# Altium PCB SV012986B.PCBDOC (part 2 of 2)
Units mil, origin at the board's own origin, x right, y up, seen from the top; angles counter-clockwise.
Board outline 2107 x 1920 mil, 4 copper layers (Top Layer, Mid-Layer 1, Mid-Layer 2, Bottom Layer), stack 59.6 mil thick; 51 components, 50 nets, 187 pads, 58 vias.
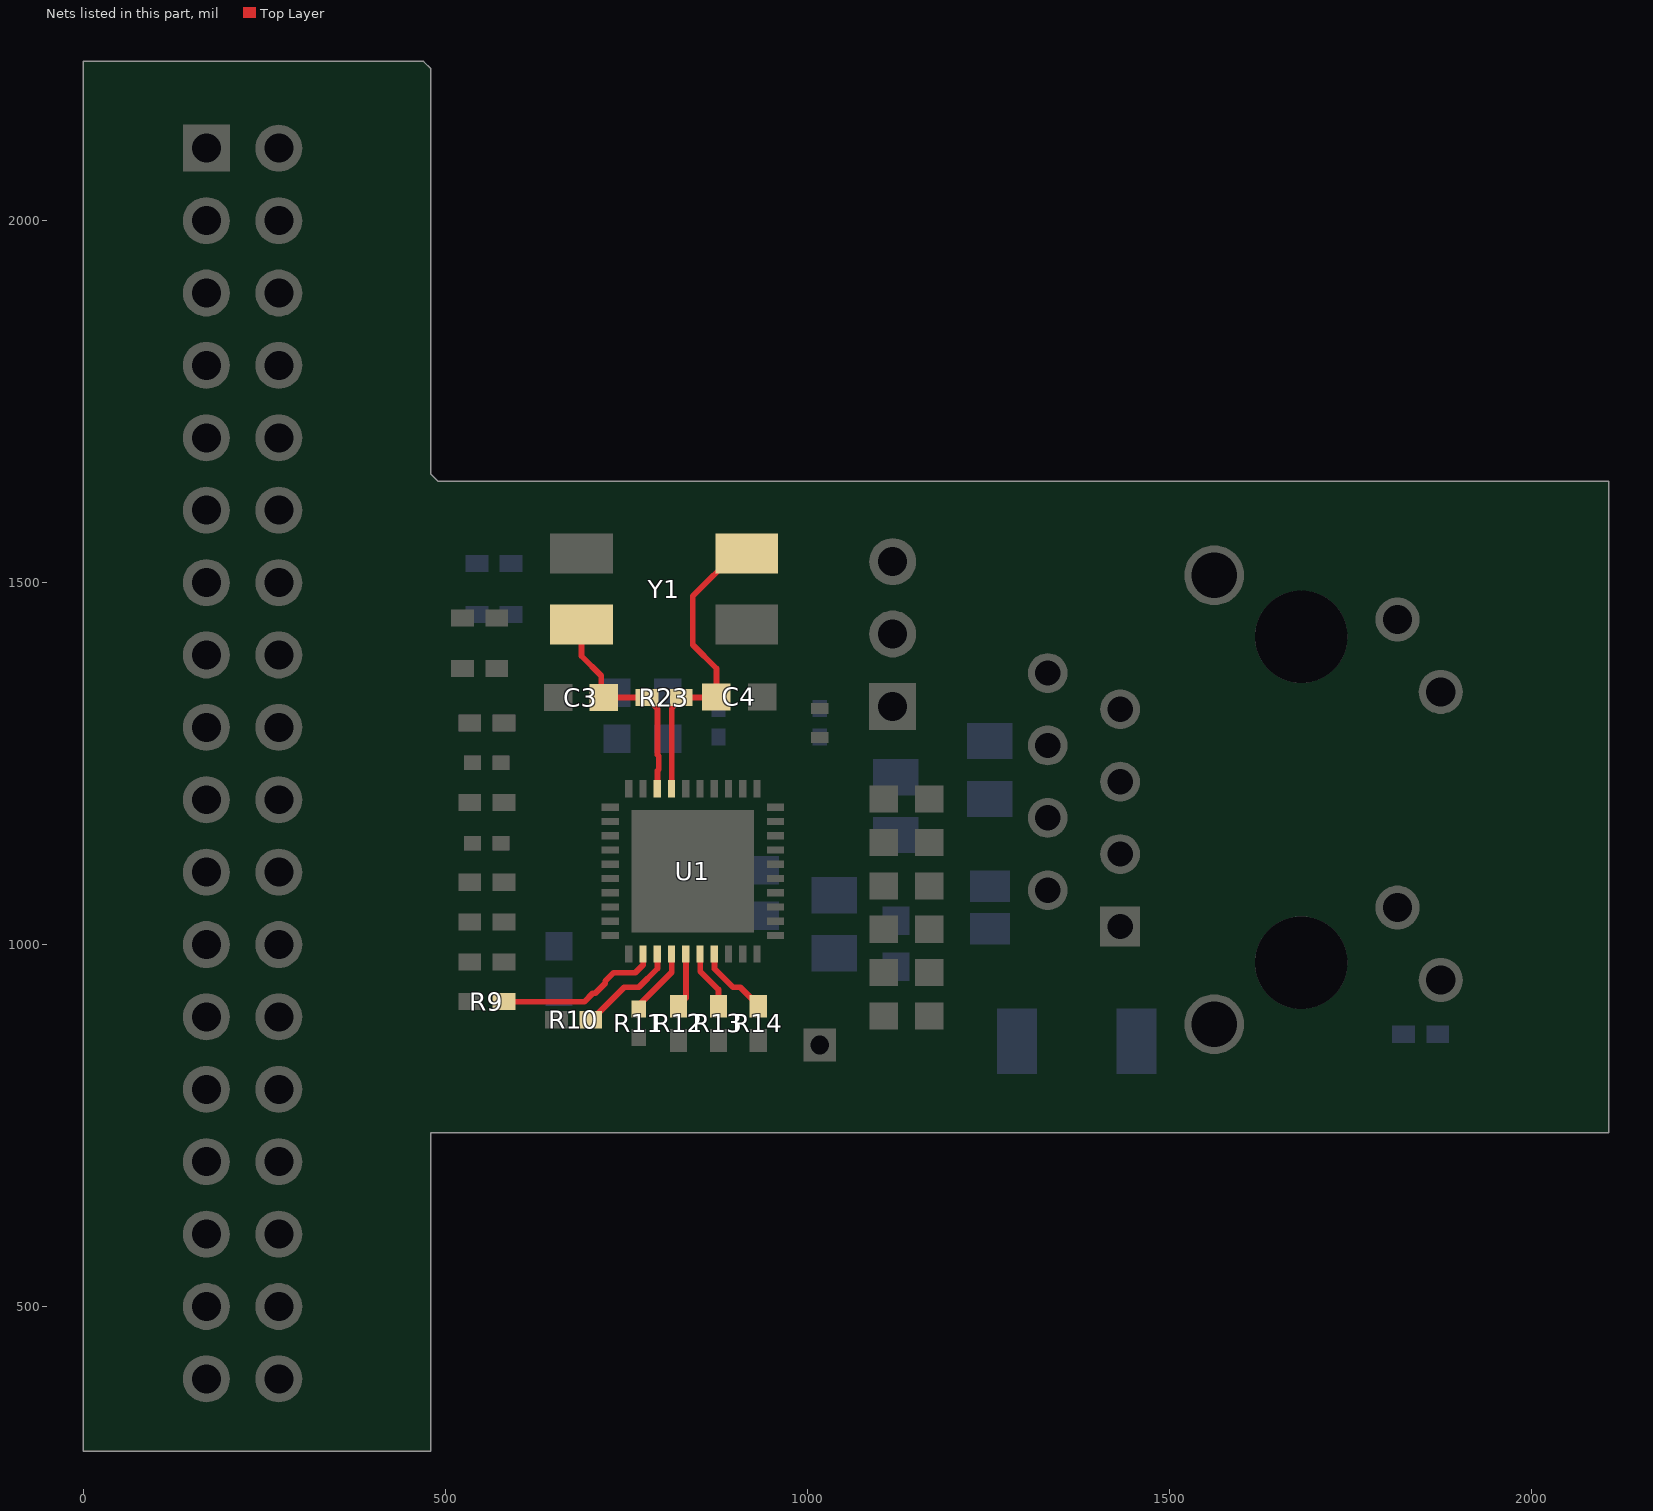
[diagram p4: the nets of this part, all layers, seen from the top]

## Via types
v1: diameter 23, hole 12, Top Layer to Bottom Layer, 50 vias
v2: diameter 19.68, hole 7.87, Top Layer to Bottom Layer, 8 vias

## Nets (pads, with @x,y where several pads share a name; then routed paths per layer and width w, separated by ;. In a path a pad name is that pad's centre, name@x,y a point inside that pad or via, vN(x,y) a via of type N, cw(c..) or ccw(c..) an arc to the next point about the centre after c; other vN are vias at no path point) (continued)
TX_CLK: R9.2 U1.2 | length 228.9
  Top Layer w8: R9.2@582.3,921.1 692.3,921.1 703.8,932.6 707.03,932.6 720.8,946.37 720.8,949.6 732.3,961.1 762.3,961.1 773.4,972.2 U1.2@773.4,986.93
TX_EN: R10.2 U1.3 | length 140.2
  Top Layer w8: R10.2@702.3,896.1 747.3,941.1 767.3,941.1 793.09,966.89 U1.3@793.09,986.93
TXD0: R11.2 U1.4 | length 89.7
  Top Layer w8: R11.2@767.3,916.1 812.77,961.57 U1.4@812.77,986.93
TXD1: R12.2 U1.5 | length 75
  Top Layer w8: R12.2@822.3,916.1 832.46,926.26 U1.5@832.46,986.93
TXD2: R13.2 U1.6 | length 81.3
  Top Layer w8: U1.6@852.14,986.93 852.14,962.86 877.3,937.7 R13.2@877.3,916.1
TXD3: R14.2 U1.7 | length 101.7
  Top Layer w8: U1.7@871.83,986.93 871.83,966.57 897.3,941.1 907.3,941.1 R14.2@932.3,916.1
X1: C3.1 R23.2 U1.28 Y1.1 | length 307.8
  Top Layer w8: Y1.1@688.13,1441.89 688.13,1398.45 715.3,1371.28 715.3,1341.1 777.3,1341.1 793.09,1325.31 793.09,1262.13 794.8,1260.42 794.8,1241.78 793.09,1240.07 U1.28@793.09,1215.27
X2: C4.1 R23.1 U1.27 Y1.3 | length 432.7
  Top Layer w8: U1.27@812.77,1215.27 812.77,1326.57 R23.1@827.3,1341.1 ; R23.1@825.92,1341.1 R23.1@827.3,1341.1 ; Y1.3@916.47,1540.31 900.72,1540.31 841.9,1481.49 841.9,1414 874.5,1381.4 C4.1@874.5,1342 873.6,1341.1 R23.1@827.3,1341.1
pads on no net: J1.20 J13.7 J13.MH1 J13.MH2 U1.8 U1.9 U1.10 U1.23

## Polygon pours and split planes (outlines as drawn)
GND on Bottom Layer "GND-GND" (solid, remove dead copper, pour order 12): 165 vertices, not listed, extent 7.3,351.1 1517.3,2151.1
GND_CHASSIS on Bottom Layer "BOTTOM-GND_CHASSIS" (solid, pour order 14): 1307.3,1576.1 1707.3,1576.1 1757.3,1526.1 1982.3,1526.1 2007.3,1501.1 2007.3,1026.1 1982.3,1001.1 1852.3,1001.1 1772.3,921.1 1772.3,856.1 1717.3,801.1 1467.3,801.1 1437.3,831.1 1437.3,906.1 1492.3,906.1 1557.3,971.1 1557.3,1251.1 1482.3,1326.1 1472.35,1326.1 1472.25,1328 1471.94,1331.48 1471.32,1334.91 1470.4,1338.28 1469.2,1341.55 1467.71,1344.71 1465.95,1347.72 1463.94,1350.57 1461.69,1353.24 1459.21,1355.7 1456.53,1357.93 1453.66,1359.92 1450.63,1361.65 1447.46,1363.11 1444.18,1364.3 1440.81,1365.19 1437.37,1365.78 1433.89,1366.07 1430.4,1366.05 1426.92,1365.74 1423.49,1365.12 1420.12,1364.2 1416.85,1363 1413.69,1361.51 1410.68,1359.75 1407.83,1357.74 1405.16,1355.49 1402.7,1353.01 1400.47,1350.33 1398.48,1347.46 1396.75,1344.43 1395.29,1341.26 1394.1,1337.98 1393.21,1334.61 1392.62,1331.17 1392.35,1328 1392.25,1326.1 1317.3,1326.1 1282.3,1361.1 1282.3,1551.1 1307.3,1576.1
PFBOUT on Bottom Layer "BOTTOM-PFBOUT" (solid, pour order 10): 767.3,1311.1 767.3,1267.95 766.02,1267.45 764.62,1266.85 763.27,1266.12 762,1265.27 760.8,1264.32 759.69,1263.27 758.68,1262.12 757.77,1260.89 756.97,1259.59 756.29,1258.22 755.73,1256.8 755.3,1255.34 755,1253.84 754.82,1252.32 754.78,1250.79 754.88,1249.27 755.1,1247.75 755.46,1246.27 755.94,1244.82 756.55,1243.42 757.28,1242.07 758.13,1240.8 759.08,1239.6 760.13,1238.49 761.28,1237.48 762.51,1236.57 763.81,1235.77 765.18,1235.09 766.6,1234.53 768.07,1234.1 769.56,1233.8 771.08,1233.62 772.61,1233.58 774.13,1233.68 775.65,1233.9 777.13,1234.26 778.58,1234.74 779.98,1235.35 780.67,1235.71 781.98,1236.42 787.3,1231.1 986.63,1231.1 986.98,1231.08 987.32,1231.04 987.67,1230.96 988,1230.86 988.32,1230.73 988.63,1230.56 988.92,1230.38 989.2,1230.16 989.46,1229.93 989.69,1229.67 989.91,1229.39 990.09,1229.1 990.26,1228.79 990.39,1228.47 990.49,1228.14 990.57,1227.79 990.61,1227.45 990.63,1227.1 990.61,1226.75 990.57,1226.41 990.49,1226.06 990.47,1225.99 990.11,1224.51 989.87,1222.99 989.77,1221.47 989.81,1219.94 989.97,1218.42 990.27,1216.92 990.7,1215.46 991.25,1214.03 991.93,1212.66 992.72,1211.35 993.63,1210.12 994.64,1208.97 995.74,1207.92 996.93,1206.96 998.2,1206.11 999.54,1205.38 1000.94,1204.76 1002.39,1204.27 1003.87,1203.91 1005.39,1203.67 1006.91,1203.57 1008.44,1203.61 1009.96,1203.77 1011.46,1204.07 1012.92,1204.5 1014.35,1205.05 1015.72,1205.73 1017.03,1206.52 1018.26,1207.43 1019.41,1208.44 1020.46,1209.54 1021.42,1210.73 1022.27,1212 1022.89,1213.11 1023.06,1213.41 1023.26,1213.7 1023.48,1213.97 1023.73,1214.22 1023.99,1214.45 1024.28,1214.65 1024.58,1214.82 1024.89,1214.97 1025.22,1215.1 1025.56,1215.19 1025.9,1215.25 1026.25,1215.28 1026.6,1215.29 1026.94,1215.26 1027.29,1215.2 1027.62,1215.11 1027.95,1215 1028.27,1214.85 1028.57,1214.68 1028.86,1214.48 1029.13,1214.26 1029.28,1214.12 1042.3,1201.1 1042.3,1126.1 1037.3,1121.1 1037.3,1106.12 1002.28,1106.12 1002.28,1071.1 932.3,1071.1 932.3,1079.08 962.32,1079.08 962.32,1119.12 932.3,1119.12 932.3,1186.1 927.3,1191.1 727.3,1191.1 702.3,1216.1 702.3,1311.1 712.3,1321.1 757.3,1321.1 767.3,1311.1
AVDD33 on Bottom Layer "BOTTOM-AVDD33" (solid, pour order 8): 1224.24,1234.92 1206.62,1217.3 1205.7,1217.38 1204.17,1217.44 1202.64,1217.37 1201.13,1217.17 1199.64,1216.83 1198.18,1216.36 1196.77,1215.77 1195.42,1215.06 1194.13,1214.24 1192.92,1213.3 1191.8,1212.26 1190.77,1211.13 1189.85,1209.92 1189.03,1208.63 1188.33,1207.27 1187.75,1205.85 1187.3,1204.39 1186.97,1202.9 1186.78,1201.38 1186.72,1199.86 1186.79,1198.33 1186.99,1196.82 1187.33,1195.32 1187.8,1193.87 1188.39,1192.46 1189.1,1191.11 1189.92,1189.82 1190.86,1188.61 1191.89,1187.49 1193.03,1186.46 1194.24,1185.53 1195.53,1184.72 1196.89,1184.02 1198.31,1183.44 1199.77,1182.98 1201.26,1182.66 1202.45,1182.49 1204.24,1182.31 1204.24,1157.53 1202.45,1157.35 1200.93,1157.13 1199.45,1156.78 1198,1156.3 1196.59,1155.69 1195.25,1154.96 1193.97,1154.12 1192.77,1153.17 1191.66,1152.12 1190.65,1150.98 1189.73,1149.76 1188.93,1148.45 1188.25,1147.09 1187.68,1145.67 1187.25,1144.2 1186.94,1142.71 1186.76,1141.19 1186.72,1139.66 1186.81,1138.13 1187.03,1136.62 1187.38,1135.13 1187.86,1133.68 1188.47,1132.28 1189.2,1130.94 1190.04,1129.66 1190.99,1128.46 1192.04,1127.35 1193.18,1126.33 1194.4,1125.42 1195.71,1124.62 1197.07,1123.94 1198.49,1123.37 1199.96,1122.93 1201.45,1122.63 1202.45,1122.49 1204.24,1122.31 1204.24,1114.92 1184.24,1094.92 1184.24,1009.92 1174.24,999.92 1084.24,999.92 1074.24,1009.92 1074.24,1114.92 1059.24,1129.92 1059.24,1174.92 1064.24,1179.92 1079.24,1179.92 1089.24,1189.92 1149.24,1189.92 1159.24,1199.92 1159.24,1324.92 1184.24,1349.92 1264.24,1349.92 1294.24,1319.92 1294.24,1244.92 1284.24,1234.92 1224.24,1234.92
GND on Mid-Layer 1 "GND-GND" (solid, remove dead copper, pour order 11): 165 vertices, not listed, extent 7.3,351.1 1517.3,2151.1
GND_CHASSIS on Top Layer "TOP-GND_CHASSIS" (solid, pour order 13): 160 vertices, not listed, extent 1282.3,821.1 2007.3,1576.1
3V3 on Mid-Layer 2 "3V3-3V3" (solid, pour order 9): 594 vertices, not listed, extent 277.3,676.1 1517.3,1681.1

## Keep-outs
Keep-Out Layer:
  text ".Layer_Name" at 577,-858.49 h60

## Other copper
Top Layer:
  text ".Layer_Name" at 577,-858.49 h60
Bottom Layer:
  text "UL94V-0" at 1527.3,1251.1 h45 r90
  text ".Layer_Name" at 577,-858.49 h60

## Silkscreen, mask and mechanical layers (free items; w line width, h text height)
Top Overlay:
  text ".Layer_Name" at 577,-858.49 h60
Bottom Overlay:
  region: 1641,1026 1641,1367 1541,1367 1541,1026
  text ".prj_title" at 103,1864 h80 r90
  text ".prj_number" at 2062,1459 h60 r90
  text ".pcb_rev" at 2062,974 h60 r90
  text ".Layer_Name" at 577,-858.49 h60
Top Paste:
  text ".Layer_Name" at 577,-858.49 h60
Bottom Paste:
  text ".Layer_Name" at 577,-858.49 h60
Top Solder:
  text ".Layer_Name" at 577,-858.49 h60
  text ".Layer_Name" at 577,-858.49 h60
Bottom Solder:
  text ".Layer_Name" at 577,-858.49 h60
Drill Guide:
  text ".Layer_Name" at 577,-858.49 h60
M1 Board Outline:
  the board outline again, w10
  text ".Layer_Name" at 577,-858.49 h60
M2 Board Dimensions:
  rectangle: 0,-275 125,-150
  rectangle: 125,-400 500,-275
  lines w7: 0,-275 1000,-275 ; 0,-150 0,-400 1000,-400 1000,-150 ; 125,-400 125,-150 ; 250,-400 250,-150 ; 500,-400 500,-150 ; 750,-400 750,-150
  text ".Layer_Name" at 577,-858.49 h60
M3 3D STEP Top:
  text ".Layer_Name" at 577,-858.49 h60
M4 3D STEP Bottom:
  text ".Layer_Name" at 577,-858.49 h60
M5 Assembly Top:
  lines w10: -292,-930.17 6308,-930.17 ; -292,-726.83 6310,-726.83 ; -292,-523.5 -292,-1133.5 3713,-1133.5 6310,-1133.5 6310,-523.5 -291.5,-523.5 -291.5,-1133.5 1284,-1133.5 ; 2173,-1133.5 2173,-523.5 ; 3440,-726.83 3440,-523.5 ; 4280,-726.83 4280,-523.5 ; 4902,-1140 4902,-937.17
  text "COMPONENTS MARKED 'DNP' SHOULD NOT BE POPULATED." at 1153.5,-318.5 h60
  text "ASSEMBLY VARIANT:" at 1153,-434 h60
  text ".VariantName" at 2189,-434 h60
  text "PCB VIEWED FROM TOP SIDE" at -228.5,-655.67 h60
  text "BOARD #:" at 2248,-655.67 h60
  text ".PRJ_Number" at 2793.5,-655.67 h60
  text "REV:" at 3638,-655.67 h60
  text ".PCB_Rev" at 3929.5,-655.67 h60
  text "SVN REV:" at 4476,-655.67 h60
  text ".VersionControl_RevNumber" at 4982,-655.67 h60
  text "PLOT NAME =" at -228.5,-1064.34 h60
  text ".plot_File_Name" at 577,-1064.34 h60
  text "GENERATED    :" at 2250,-1064.34 h60
  text ".Print_Date" at 3119.5,-1064.34 h60
  text ".Print_Time" at 3848.5,-1064.34 h60
  text "TEXAS INSTRUMENTS" at 5113,-1064.34 h60
M6 Assembly Bottom:
  lines w10: -292.5,-727.33 6309.5,-727.33 ; -290.5,-930.67 6309.5,-930.67 ; 1115.5,-1140.5 1115.5,-937.67 ; 1737.5,-727.33 1737.5,-524 ; 2577.5,-727.33 2577.5,-524 ; 3844.5,-1134 3844.5,-524 ; 4733.5,-1134 6309,-1134 6309,-524 -292.5,-524 -292.5,-1134 2304.5,-1134 6309.5,-1134 6309.5,-524
  text "COMPONENTS MARKED 'DNP' SHOULD NOT BE POPULATED." at 6102,-318 h60
  text ".VariantName" at 5058,-434 h60
  text "ASSEMBLY VARIANT:" at 6097,-434 h60
  text ".VersionControl_RevNumber" at 1035.5,-656.17 h60
  text "SVN REV:" at 1541.5,-656.17 h60
  text ".PCB_Rev" at 2088,-656.17 h60
  text "REV:" at 2379.5,-656.17 h60
  text ".PRJ_Number" at 3224,-656.17 h60
  text "BOARD #:" at 3769.5,-656.17 h60
  text "PCB VIEWED FROM BOTTOM SIDE" at 6246,-656.17 h60
  text "TEXAS INSTRUMENTS" at 904.5,-1064.84 h60
  text ".Print_Time" at 2169,-1064.84 h60
  text ".Print_Date" at 2898,-1064.84 h60
  text "GENERATED    :" at 3767.5,-1064.84 h60
  text ".plot_File_Name" at 5440.5,-1064.84 h60
  text "PLOT NAME =" at 6246,-1064.84 h60
M9 Title Sheet:
  drawing of 57 lines, arcs and shapes, not listed
  text "1" at 739.84,8036.5 h70
  text "2" at 3235.5,8036.5 h70
  text "3" at 5724.84,8036.5 h70
  text "4" at 8231.51,8036.5 h70
  text "5" at 10730.5,8036.5 h70
  text "6" at 13235.5,8036.5 h70
  text "A" at -416.5,6893.5 h70
  text "A" at 14383.5,6893.5 h70
  text "B" at -416.5,4513.5 h70
  text "B" at 14383.5,4513.5 h70
  text "C" at -416.5,2138.5 h70
  text "C" at 14383.5,2138.5 h70
  text "PROJECT TITLE:" at 11343.5,277.5 h45
  text ".PRJ_Title" at 11393.5,144.17 h70
  text "DESIGNED FOR:" at 11343.5,-23.5 h45
  text ".PRJ_Customer" at 11393.5,-163.5 h70
  text "D" at -416.5,-231.5 h70
  text "D" at 14383.5,-231.5 h70
  text "FILE NAME:" at 11343.5,-323.5 h45
  text ".PCB_File_Name_No_Path" at 11393.5,-443.5 h70
  text "Texas Instruments (TI) and/or its licensors do not warrant the accuracy or completeness of this specification" at 6374,-605.34 h45
  text "ENGINEER:" at 11343.5,-613.5 h45
  text "LAYOUT BY:" at 12848.5,-613.5 h45
  text "or any information contained therein. TI and/or its licensors do not warrant that this design will meet" at 6329.01,-718 h45
  text ".PRJ_Engineer" at 11393.5,-768.49 h70
  text ".PCB_Layout" at 12899,-768.49 h70
  text "the specifications, will be suitable for your application or fit for any particular purpose, or will operate in" at 6329.01,-830.67 h45
  text ".Layer_Name" at 577,-858.49 h60
  text "ALTIUM DESIGNER VERSION:" at 12848.5,-923.5 h45
  text "an implementation. TI and/or its licensors do not warrant that the design is production worthy. You should" at 6329.01,-943.33 h45
  text "completely validate and test your design implementation to confirm the system functionality for your application." at 6374,-1056 h45
  text ".print_Scale" at 11393.5,-1056.83 h70
  text ".Application_BuildNumber" at 12899,-1056.83 h70
  text "1" at 739.84,-1263.5 h70
  text "2" at 3235.5,-1263.5 h70
  text "3" at 5724.84,-1263.5 h70
  text "4" at 8231.51,-1263.5 h70
  text "5" at 10730.5,-1263.5 h70
  text "6" at 13235.5,-1263.5 h70
M10 Fab Notes:
  drawing of 185 lines, arcs and shapes, not listed
  text "DESIGN INFORMATION" at 12381.02,5910 h60
  text "MIN. TRACK WIDTH:" at 11736.46,5730 h60
  text "8" at 12832.7,5730 h60
  text "MIL" at 12987.46,5730 h60
  text "MIN. CLEARANCE:" at 11736.46,5598 h60
  text "0.2" at 12772.7,5598 h60
  text "mm" at 12987.46,5598 h60
  text "MIN. VIA PAD SIZE:" at 11736.46,5466 h60
  text "24" at 12802.71,5466 h60
  text "MIL" at 12987.46,5466 h60
  text "0.05mm (2MIL)" at 12431.46,5324.29 h60
  text "MINIMUM ANNULAR RING" at 11407.23,5320 h60
  text "EXTERNAL" at 13139.46,5320 h60
  text "PER" at 11607.23,5202 h60
  text "IPC-D-275 CLASS 2 LEVEL C" at 11827.23,5202 h60
  text "MIL, HOLES" at 13315.46,5089.71 h60
  text "+/-" at 12923,5089 h60
  text "+/-" at 13777,5089 h60
  text "REGISTRATION TOLERANCES:" at 11407.23,5084 h60
  text "METAL" at 12607,5084 h60
  text "5" at 13183.2,5084 h60
  text "3" at 14016.2,5084 h60
  text "MIL" at 14132.46,5084 h60
  text "MATERIAL:" at 11332.46,4874.54 h60
  text "FR-4 High Tg" at 12318.9,4734.21 h60
  text "FR-408" at 11753.46,4725.64 h60
  text "X" at 12165.46,4725.64 h60
  text "OTHER" at 13241.46,4725.64 h60
  text "62 MIL (1.6mm) +/-10%" at 12073.56,4562.92 h60
  text "THICKNESS:" at 11407.23,4558.64 h60
  text "X" at 11945.4,4558.64 h60
  text "OTHER" at 13358.46,4558.64 h60
  text "TOLERANCE:" at 11407.23,4400.64 h60
  text "X" at 12246.53,4400.64 h60
  text "ANSI IPC-6012 TYPE 3 CLASS 2" at 12433.48,4400.64 h60
  text "OTHER +/-" at 12433.46,4244.64 h60
  text "BOW & TWIST:" at 11407.23,4087.64 h60
  text "X" at 12246.53,4087.64 h60
  text "ANSI IPC-6012 TYPE 3 CLASS 2" at 12433.48,4087.64 h60
  text "OTHER +/-" at 12433.46,3929.13 h60
  text "DRILLING:" at 11332.46,3790.64 h60
  text "REFERENCE:" at 11407.23,3673.64 h60
  text "X" at 12055.46,3673.64 h60
  text "AS SHOWN" at 12242.46,3673.64 h60
  text "X" at 12956.46,3673.64 h60
  text "NC_DRILL FILES" at 13093.46,3673.64 h60
  text "PTH MIN COPPER THICKNESS:" at 11407.23,3515.64 h60
  text "X" at 12757.46,3515.64 h60
  text "1MIL" at 12894.46,3515.64 h60
  text "OTHER" at 13391.46,3515.64 h60
  text "BOARD FINISH:" at 11332.46,3356.64 h60
  text "SILKSCREEN:" at 11487.68,3238.64 h60
  text "X" at 12436.46,3238.64 h60
  text "TOP" at 12562.46,3238.64 h60
  text "X" at 12946.46,3238.64 h60
  text "BOTTOM" at 13073.46,3238.64 h60
  text "SILKSCREEN COLOR:" at 11487.68,3071.64 h60
  text "X" at 12435.42,3071.64 h60
  text "WHITE" at 12562.46,3071.64 h60
  text "OTHER" at 13073.46,3071.64 h60
  text "SOLDER RESIST COLOR:" at 11487.68,2901.64 h60
  text "X" at 12055.42,2742.44 h60
  text "GREEN" at 12182.46,2742.44 h60
  text "BLUE" at 12773.46,2742.44 h60
  text "OTHER" at 13311.46,2742.44 h60
  text "IMMERSION GOLD (ENIG)" at 12393.46,2553.92 h60
  text "ENEPIG" at 13731,2550.64 h60
  text "SURFACE FINISH:" at 11332.46,2549.64 h60
  text "X" at 12206.51,2549.64 h60
  text "IMM. TIN/SILVER OR EQUIV" at 11662,2392.64 h60
  text "OTHER" at 13093.46,2392.64 h60
  text "ARRAY/PANEL:" at 11332.46,2213.64 h60
  text "CUT AND TRIM PER MECH LAYER 1" at 12393.46,2209.35 h60
  text "N.C. ROUTE" at 12393.46,2057.64 h60
  text "X" at 13072.46,2057.64 h60
  text "V. SCORE" at 13259.46,2057.64 h60
  text "CERTIFICATION:" at 11332.46,1920.64 h60
  text "MATERIALS AND WORKMANSHIP FOR ALL PCBS" at 12057.46,1920.64 h60
  text "TO MEET OR EXCEED THE REQUIREMENTS OF:" at 12057.46,1822.64 h60
  text "X" at 11683.96,1686.13 h60
  text "ANSI IPC-A-600F CLASS ->" at 11822.96,1686.13 h60
  text "X" at 13462.02,1686.13 h60
  text "2" at 13580.96,1686.14 h60
  text "1" at 13265.96,1684.64 h60
  text "3" at 13934.96,1684.64 h60
  text "X" at 11686.02,1526.64 h60
  text "UL 94V-0" at 11822.96,1526.64 h60
  text "X" at 12498.02,1526.64 h60
  text "RoHS" at 12634.96,1526.64 h60
  text "OTHER" at 13279.36,1526.64 h60
  text "PER ORDER" at 13676.42,1526.64 h60
  text "ADDITIONAL REQUIREMENTS:" at 11332.46,1385.64 h60
  text "MICROSECTION:" at 11407.23,1270.64 h60
  text "YES" at 12312.96,1270.64 h60
  text "REQUIRED" at 13174.46,1114.49 h60
  text "BARE BOARD ELEC. TEST:" at 11407.23,1111.64 h60
  text "NONE" at 12712.96,1111.64 h60
  text "X" at 13047.46,1111.64 h60
  text "PER ORDER" at 13766.46,1111.64 h60
  text "MANUFACTURER'S UL:" at 11407.23,954.64 h60
  text "RAIL" at 12572.96,950.35 h60
  text "METAL" at 13064.77,950.35 h60
  text "X" at 13440,950 h60
  text "SILK" at 13576.46,950.35 h60
  text ".Layer_Name" at 577,-858.49 h60
M11 Gerber Information:
  lines w10: -292,-930.17 6308,-930.17 ; -292,-726.83 6310,-726.83 ; -292,-523.5 -292,-1133.5 3713,-1133.5 6310,-1133.5 6310,-523.5 -291.5,-523.5 -291.5,-1133.5 1284,-1133.5 ; 2173,-1133.5 2173,-523.5 ; 3440,-726.83 3440,-523.5 ; 4280,-726.83 4280,-523.5 ; 4902,-1140 4902,-937.17
  text "ALL ARTWORK VIEWED FROM TOP SIDE" at -228.5,-655.67 h60
  text "BOARD #:" at 2248,-655.67 h60
  text ".PRJ_Number" at 2793.5,-655.67 h60
  text "REV:" at 3638,-655.67 h60
  text ".PCB_Rev" at 3929.5,-655.67 h60
  text "SVN REV:" at 4476,-655.67 h60
  text ".VersionControl_RevNumber" at 4982,-655.67 h60
  text "LAYER NAME =" at -228.5,-858.49 h60
  text "PLOT NAME =" at -228.5,-1064.34 h60
  text ".plot_File_Name" at 577,-1064.34 h60
  text "GENERATED    :" at 2250,-1064.34 h60
  text ".Print_Date" at 3119.5,-1064.34 h60
  text ".Print_Time" at 3848.5,-1064.34 h60
  text "TEXAS INSTRUMENTS" at 5113,-1064.34 h60
M12 Stackup:
  drawing of 295 lines, arcs and shapes, not listed
  text "Layer" at 4550,5940 h60
  text "Name" at 4959.91,5940 h60
  text "Material" at 5889.66,5940 h60
  text "Thickness" at 6749.42,5940 h60
  text "Constant" at 7399.26,5940 h60
  text "Board Layer Stack" at 7969.12,5940 h60
  text "1" at 4550,5820 h60
  text "Top Overlay" at 4959.91,5820 h60
  text "2" at 4550,5700 h60
  text "Top Solder" at 4959.91,5700 h60
  text "Solder Resist" at 5889.66,5700 h60
  text "0.40mil" at 6749.42,5700 h60
  text "3.5" at 7399.26,5700 h60
  text "3" at 4550,5580 h60
  text "Top Layer" at 4959.91,5580 h60
  text "Copper" at 5889.66,5580 h60
  text "1.40mil" at 6749.42,5580 h60
  text "4" at 4550,5460 h60
  text "Dielectric1" at 4959.91,5460 h60
  text "FR-4" at 5889.66,5460 h60
  text "4.00mil" at 6749.42,5460 h60
  text "4.8" at 7399.26,5460 h60
  text "5" at 4550,5340 h60
  text "Mid-Layer 1" at 4959.91,5340 h60
  text "Copper" at 5889.66,5340 h60
  text "1.40mil" at 6749.42,5340 h60
  text "6" at 4550,5220 h60
  text "Dielectric3" at 4959.91,5220 h60
  text "FR-4" at 5889.66,5220 h60
  text "46.00mil" at 6749.42,5220 h60
  text "4.8" at 7399.26,5220 h60
  text "7" at 4550,5100 h60
  text "Mid-Layer 2" at 4959.91,5100 h60
  text "Copper" at 5889.66,5100 h60
  text "1.40mil" at 6749.42,5100 h60
  text "8" at 4550,4980 h60
  text "Dielectric2" at 4959.91,4980 h60
  text "FR-4" at 5889.66,4980 h60
  text "4.00mil" at 6749.42,4980 h60
  text "4.8" at 7399.26,4980 h60
  text "9" at 4550,4860 h60
  text "Bottom Layer" at 4959.91,4860 h60
  text "Copper" at 5889.66,4860 h60
  text "1.40mil" at 6749.42,4860 h60
  text "10" at 4550,4740 h60
  text "Bottom Solder" at 4959.91,4740 h60
  text "Solder Resist" at 5889.66,4740 h60
  text "0.40mil" at 6749.42,4740 h60
  text "3.5" at 7399.26,4740 h60
  text "11" at 4550,4620 h60
  text "Bottom Overlay" at 4959.91,4620 h60
  text ".Layer_Name" at 577,-858.49 h60
M13 Component Bodies Top:
  text ".Layer_Name" at 577,-858.49 h60
M14 Component Bodies Bottom:
  text ".Layer_Name" at 577,-858.49 h60
M15 Courtyards Top:
  text ".Layer_Name" at 577,-858.49 h60
M16 Courtyards Bottom:
  text ".Layer_Name" at 577,-858.49 h60
Drill Drawing:
  circle w1: c5692.73,3071.68 r24.89
  lines w1: 5667.84,2175.67 5692.73,2150.78 5717.62,2175.67 5692.73,2200.56 5667.84,2175.67 ; 5667.84,2300.12 5667.84,2312.56 5680.28,2325.01 5667.84,2337.45 5667.84,2349.9 5680.28,2349.9 5692.73,2337.45 5705.17,2349.9 5717.62,2349.9 5717.62,2337.45 5705.17,2325.01 5717.62,2312.56 5717.62,2300.12 5705.17,2300.12 5692.73,2312.56 5680.28,2300.12 5667.84,2300.12 ; 5667.84,2461.9 5680.28,2461.9 5680.28,2449.45 5705.17,2449.45 5705.17,2461.9 5717.62,2461.9 5717.62,2486.79 5705.17,2486.79 5705.17,2499.23 5680.28,2499.23 5680.28,2486.79 5667.84,2486.79 5667.84,2461.9 ; 5667.84,2598.79 5692.73,2611.23 5717.62,2598.79 5705.17,2623.68 5717.62,2648.57 5692.73,2636.12 5667.84,2648.57 5680.28,2623.68 5667.84,2598.79 ; 5667.84,2760.57 5680.28,2760.57 5692.73,2748.12 5705.17,2760.57 5717.62,2760.57 5705.17,2773.01 5717.62,2785.46 5705.17,2785.46 5692.73,2797.9 5680.28,2785.46 5667.84,2785.46 5680.28,2773.01 5667.84,2760.57 ; 5667.84,2947.24 5717.62,2947.24 5692.73,2897.46 5667.84,2947.24 ; 5667.84,3196.13 5717.62,3196.13 5717.62,3245.91 5667.84,3245.91 5667.84,3196.13 ; 5677.79,3206.09 5707.66,3206.09 5707.66,3235.95 5677.79,3235.95 5677.79,3206.09
  lines w12: 5600,2105.98 7716.94,2105.98 ; 5600,3300.66 7716.94,3300.66 ; 5970.25,1956.65 5970.25,3450 ; 6327.06,1956.65 6327.06,3450 ; 6988.16,1956.65 6988.16,3450 ; 7272.16,1956.65 7272.16,3450 ; 5600,1956.65 7716.94,1956.65 7716.94,3450 5600,3450 5600,1956.65
  text "Symbol" at 5689.6,3345.47 h72
  text "Quantity" at 6015.05,3345.47 h72
  text "Finished Hole Size" at 6371.86,3345.47 h72
  text "Plated" at 7032.96,3345.47 h72
  text "Hole Type" at 7316.96,3345.47 h72
  text "2" at 6015.05,3196.13 h60
  text "127.95mil (3.250mm)" at 6371.86,3196.13 h60
  text "NPTH" at 7032.96,3196.13 h60
  text "Round" at 7316.96,3196.13 h60
  text "8" at 6015.05,3046.8 h60
  text "7.87mil (0.200mm)" at 6371.86,3046.8 h60
  text "PTH" at 7032.96,3046.8 h60
  text "Round" at 7316.96,3046.8 h60
  text "50" at 6015.05,2897.46 h60
  text "12.00mil (0.305mm)" at 6371.86,2897.46 h60
  text "PTH" at 7032.96,2897.46 h60
  text "Round" at 7316.96,2897.46 h60
  text "1" at 6015.05,2748.12 h60
  text "26.00mil (0.660mm)" at 6371.86,2748.12 h60
  text "PTH" at 7032.96,2748.12 h60
  text "Round" at 7316.96,2748.12 h60
  text "8" at 6015.05,2598.79 h60
  text "35.04mil (0.890mm)" at 6371.86,2598.79 h60
  text "PTH" at 7032.96,2598.79 h60
  text "Round" at 7316.96,2598.79 h60
  text "39" at 6015.05,2449.45 h60
  text "40.00mil (1.016mm)" at 6371.86,2449.45 h60
  text "PTH" at 7032.96,2449.45 h60
  text "Round" at 7316.96,2449.45 h60
  text "4" at 6015.05,2300.12 h60
  text "40.16mil (1.020mm)" at 6371.86,2300.12 h60
  text "PTH" at 7032.96,2300.12 h60
  text "Round" at 7316.96,2300.12 h60
  text "2" at 6015.05,2150.78 h60
  text "62.99mil (1.600mm)" at 6371.86,2150.78 h60
  text "PTH" at 7032.96,2150.78 h60
  text "Round" at 7316.96,2150.78 h60
  text "114 Total" at 6015.05,2001.45 h60
  text ".Layer_Name" at 577,-858.49 h60

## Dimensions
0,-400 to 1000,-400 on M2 Board Dimensions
